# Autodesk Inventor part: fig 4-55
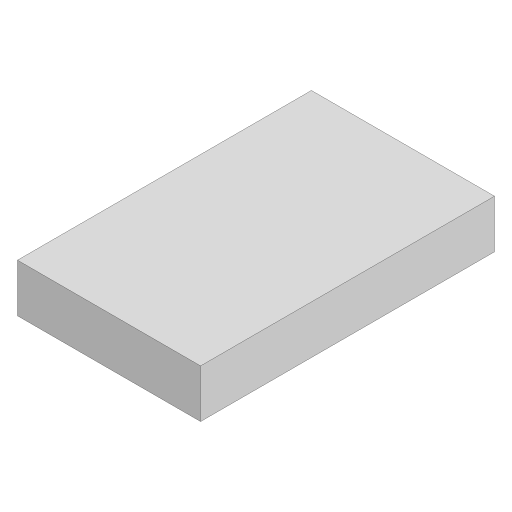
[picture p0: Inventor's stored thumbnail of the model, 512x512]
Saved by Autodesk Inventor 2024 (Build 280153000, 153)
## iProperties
Created: 2023-08
Part Number: fig 4-55
Material: Generic
Document SubType Name: Modeling
Designer: LENOVO-CADCIM
Density: 1 g/cm^3
Appearance: Default
Author: LENOVO-CADCIM
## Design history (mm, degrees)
sketch "Sketch1"
  geometry: L1 (0, 0)-(38, 0); L2 (38, 0)-(38, -61); L3 (38, -61)-(0, -61); L4 (0, -61)-(0, 0)
  constraints: 8 end point, 2 parallel, 1 horizontal, 1 perpendicular
extrude "Extrusion1" new body sketch "Sketch1" distance "d0" = 10; taper "d1" = 0 deg
body "Solid1"
